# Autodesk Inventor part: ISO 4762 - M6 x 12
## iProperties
Created: 2007-03
Part Number: ISO 4762 - M6 x 12
Material: Stainless Steel, 440C
Description: Hexagon Socket Head Cap Screw
Document SubType Name: Modeling
Standard: ISO 4762
Designer: Admin
Standard Revision: Fourth edition 2004-03-01
Standards Organization: ISO
Language: en-US
Size Designation: M6 x 12
Categories: <MemberInstance><Categories><Category DisplayName="Fasteners" InternalName="e4da775c-781d-43d5-af7c-5136215cf5a6" Mnemonic="FSTN"><Category DisplayName="Bolts"
Density: 1 g/cm^3
IsCustomPart: 0
Author: Admin
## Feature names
1. Body [Revolution]
2. Slot [Extrusion]
3. Fillet1
4. Chamfer1
5. Fillet2
